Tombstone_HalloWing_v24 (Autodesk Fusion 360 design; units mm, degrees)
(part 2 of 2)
sketch "Sketch16" plane through (0, 0, 0) normal (1, 0, 0) x axis (0, 1, 0)
  curve K1 (-0.5, 161.7636) -> (4.5, 161.7636)
  line L1 (10, 161.7636) -> (4.5, 161.7636)
  line L2 (10, 180) -> (10, 161.7636)
  line L3 (-6, 180) -> (10, 180)
  line L4 (-6, 161.7636) -> (-6, 180)
  line L5 (-0.5, 161.7636) -> (-6, 161.7636)
  curve K2 (2, 168) -> (2, 177)
  curve K3 (7.5, 172.5) -> (-3.5, 172.5)
  line L6 (-2, 164.9114) -> (-2, 169.4114)
  line L7 (0.394, 166.2936) -> (-2, 164.9114)
  line L8 (2, 164) -> (0.394, 166.2936)
  curve K4 (-0.5, 171) -> (-0.5, 175)
  curve K5 (1.25, 173) -> (-2.25, 173)
  line L9 (2, 177) -> (2, 180)
  line L10 (3.4434, 169) -> (0.5566, 169)
  line L11 (2, 171.5) -> (3.4434, 169)
  line L12 (0.5566, 169) -> (2, 171.5)
  line L13 (2, 169) -> (2, 171.5)
  line L14 (2, 168) -> (2, 164)
  line L15 (2, 164) -> (3.606, 166.2936)
  line L16 (3.606, 166.2936) -> (6, 164.9114)
  line L17 (6, 164.9114) -> (6, 169.4114)
  closed curve K6 centre (2, 172.5)
  closed curve K7 centre (-0.5, 173)
  closed curve K8 centre (4.5, 173)
  point P9 (2, 177)
  point P10 (2, 168)
  point P11 (-3.5, 172.5)
  point P12 (7.5, 172.5)
  point P13 (-2, 169.4114)
  point P18 (-0.5, 175)
  point P19 (-0.5, 171)
  point P20 (-2.25, 173)
  point P21 (1.25, 173)
  point P22 (2, 180)
  point P28 (2, 169)
  point P32 (6, 169.4114)
  point P14 (-2, 164.9114)
  point P31 (6, 164.9114)
  point P15 (0.394, 166.2936)
  point P29 (3.606, 166.2936)
  point P16 (2, 164)
  point P30 (2, 164)
  point P23 (2, 177)
  point P27 (2, 171.5)
  point P8 (2, 172.5)
  vertical K2
  coincident K6 P9
  coincident K6 P10
  coincident K6 P11
  coincident K6 P12
  coincident K6 P13
  vertical L6
  coincident K7 P18
  coincident K7 P19
  coincident K7 P20
  coincident K7 P21
  midpoint L3 P22
  perpendicular L3 L9
  symmetric K7 L9 K8
  perpendicular K2 L10
  midpoint L10 P28
  vertical L13
  collinear K2 L13
  vertical L14
  symmetric P13 L14 P32
  symmetric P14 L14 P31
  symmetric P15 L14 P29
  symmetric P16 L14 P30
  coincident P9 P23
  dimension "d450" distance K6 = 9
  dimension "d451" = 11
  dimension "d452" = 3.5
  dimension "d453" distance K7 = 4
  dimension "d454" angle L11 L12 = 60
  dimension "d455" distance P27 P28 = 2.5
  dimension "d456" angle L8 L14 = 35
  dimension "d457" distance P10 P16 = 4
  dimension "d458" distance P13 P14 = 4.5
  dimension "d459" distance L6 L14 = 4
  dimension "d464" distance P22 P23 = 3
  dimension "d465" distance K3 K5 = 0.5
  dimension "d466" distance K2 K4 = 2.5
  dimension "d467" distance P8 P27 = 1
  dimension "d468" angle L6 L7 = 60
extrude "Extrude22" sketch "Sketch16" profile of K6 L6 L7 L8 K7 K8 L10 L11 L12 L15 L16 L17 blind 2
chamfer "Chamfer19" distance 1
extrude "Extrude23" cut of existing geometry blind -1
extrude "Extrude24" sketch "Sketch16" profile of K7 K8 L10 L11 L12 blind -0.5
chamfer "Chamfer20" distance 0.5
mirror "Mirror12" mirrorStitchTolerance 0.1
sketch "project face plate" plane through (0, -2, 0) normal (0, -1, 0) x axis (1, 0, 0)
  line L1 (52.2, 42) -> (52.2, 24)
  line L2 (54, 43) -> (53.2, 43)
  line L3 (53.2, 50) -> (54, 50)
  line L4 (52.2, 142) -> (52.2, 51)
  line L5 (54, 143) -> (53.2, 143)
  line L6 (53.2, 150) -> (54, 150)
  line L7 (52.2, 168.2) -> (52.2, 151)
  line L8 (37.9684, 170.2) -> (50.2, 170.2)
  line L9 (-50.2, 170.2) -> (-37.9684, 170.2)
  line L10 (-52.2, 151) -> (-52.2, 168.2)
  line L11 (-54, 150) -> (-53.2, 150)
  line L12 (-53.2, 143) -> (-54, 143)
  line L13 (-52.2, 51) -> (-52.2, 142)
  line L14 (-54, 50) -> (-53.2, 50)
  line L15 (-53.2, 43) -> (-54, 43)
  line L16 (-52.2, 24) -> (-52.2, 42)
  line L17 (50.2, 22) -> (-50.2, 22)
  line L18 (36, 37.2952) -> (36, 136.7048)
  line L19 (-36, 136.7048) -> (-36, 37.2952)
  line L20 (50.2, 168.2) -> (-50.2, 168.2)
  line L21 (50.2, 24) -> (50.2, 168.2)
  line L22 (-50.2, 24) -> (50.2, 24)
  line L23 (-50.2, 168.2) -> (-50.2, 24)
  circle C1 centre (13.8, 192.063) radius 2.5
  arc A1 centre (50.2, 24) radius 2 clockwise from (52.2, 24) to (50.2, 22)
  arc A2 centre (53.2, 42) radius 1 clockwise from (52.2, 42) to (53.2, 43)
  arc A3 centre (54, 46.5) radius 3.5 clockwise from (54, 50) to (54, 43)
  arc A4 centre (53.2, 51) radius 1 clockwise from (53.2, 50) to (52.2, 51)
  arc A5 centre (53.2, 142) radius 1 clockwise from (52.2, 142) to (53.2, 143)
  arc A6 centre (54, 146.5) radius 3.5 clockwise from (54, 150) to (54, 143)
  arc A7 centre (53.2, 151) radius 1 clockwise from (53.2, 150) to (52.2, 151)
  arc A8 centre (50.2, 168.2) radius 2 clockwise from (50.2, 170.2) to (52.2, 168.2)
  arc A9 centre (37.9684, 172.2) radius 2 clockwise from (37.9684, 170.2) to (35.9805, 171.9801)
  arc A10 centre (0, 168) radius 36.2 clockwise from (-35.9805, 171.9801) to (35.9805, 171.9801)
  arc A11 centre (-37.9684, 172.2) radius 2 clockwise from (-35.9805, 171.9801) to (-37.9684, 170.2)
  arc A12 centre (-50.2, 168.2) radius 2 clockwise from (-52.2, 168.2) to (-50.2, 170.2)
  arc A13 centre (-53.2, 151) radius 1 clockwise from (-52.2, 151) to (-53.2, 150)
  arc A14 centre (-54, 146.5) radius 3.5 clockwise from (-54, 143) to (-54, 150)
  arc A15 centre (-53.2, 142) radius 1 clockwise from (-53.2, 143) to (-52.2, 142)
  arc A16 centre (-53.2, 51) radius 1 clockwise from (-52.2, 51) to (-53.2, 50)
  arc A17 centre (-54, 46.5) radius 3.5 clockwise from (-54, 43) to (-54, 50)
  arc A18 centre (-53.2, 42) radius 1 clockwise from (-53.2, 43) to (-52.2, 42)
  arc A19 centre (-50.2, 24) radius 2 clockwise from (-50.2, 22) to (-52.2, 24)
  circle C2 centre (-54, 46.5) radius 1.75
  circle C3 centre (-54, 146.5) radius 1.75
  circle C4 centre (54, 46.5) radius 1.75
  circle C5 centre (54, 146.5) radius 1.75
  arc A20 centre (0, -56) radius 100 clockwise from (-36, 37.2952) to (36, 37.2952)
  arc A21 centre (0, 230) radius 100 clockwise from (36, 136.7048) to (-36, 136.7048)
  circle C6 centre (0, 168) radius 34.2
  point P36 (-50.2, 168.2)
  point P64 (-50.2, 168.2)
  point P26 (50.2, 168.2)
  point P65 (50.2, 168.2)
  point P5 (50.2, 24)
  point P66 (50.2, 24)
  point P57 (-50.2, 24)
  point P67 (-50.2, 24)
  coincident P36 P64
  coincident P26 P65
  coincident P5 P66
  coincident P57 P67
  concentric A10 C6
  dimension "d478" distance A10 C6 = 2
extrude "Extrude14" new body sketch "project face plate" profile of C1 L18 A20 L19 A21 L20 L21 L22 L23 C6 along normal blind 1 bodies "plate vinyl"
sketch "face plate vinyl" plane through (0, -3, 0) normal (0, -1, 0) x axis (1, 0, 0)
  curve K1 (0, 184.5) -> (-15.4989, 168.2)
  curve K2 (15.4989, 168.2) -> (0, 184.5)
  curve K3 (-15.4989, 168.2) -> (15.4989, 168.2)
  line L1 (-36, 136.7048) -> (-36, 37.2952)
  line L2 (36, 37.2952) -> (36, 136.7048)
  line L3 (-50.2, 168.2) -> (-34.1994, 168.2)
  line L4 (-50.2, 24) -> (-50.2, 168.2)
  line L5 (50.2, 24) -> (-50.2, 24)
  line L6 (50.2, 168.2) -> (50.2, 24)
  line L7 (34.1994, 168.2) -> (50.2, 168.2)
  circle C1 centre (13.8, 192.063) radius 2.5
  arc A1 centre (0, 230) radius 100 clockwise from (36, 136.7048) to (-36, 136.7048)
  arc A2 centre (0, -56) radius 100 clockwise from (-36, 37.2952) to (36, 37.2952)
  arc A3 centre (0, 168) radius 34.2 clockwise from (-34.1994, 168.2) to (34.1994, 168.2)
sketch "bottom lip" plane through (0, 28, 0) normal (0, -1, 0) x axis (1, 0, 0)
  line L1 (-55, 22) -> (55, 22)
  line L2 (45, 23.5) -> (-45, 23.5)
  line L3 (45, 22) -> (45, 23.5)
  line L4 (-45, 22) -> (45, 22)
  line L5 (-45, 23.5) -> (-45, 22)
  line L6 (36.8782, 171) -> (53, 171)
  line L7 (52.8, 170.8) -> (37.0782, 170.8)
  line L8 (52.8, 169.3) -> (52.8, 170.8)
  line L9 (37.0782, 169.3) -> (52.8, 169.3)
  line L10 (37.0782, 170.8) -> (37.0782, 169.3)
  line L11 (44.9391, 171) -> (44.9391, 170.8)
  line L12 (52.8, 169.3) -> (51.3, 169.3)
  line L13 (52.8, 155.3) -> (52.8, 169.3)
  line L14 (51.3, 155.3) -> (52.8, 155.3)
  line L15 (51.3, 169.3) -> (51.3, 155.3)
  point P14 (44.9391, 170.8)
  point P15 (44.9391, 171)
  point P12 (52.8, 169.3)
  point P17 (52.8, 169.3)
  point P4 (-45, 23.5)
  point P5 (45, 23.5)
  point P7 (-45, 22)
  point P10 (37.0782, 170.8)
  point P13 (37.0782, 169.3)
  point P9 (36.8782, 171)
  point P16 (51.3, 169.3)
  point P19 (51.3, 155.3)
  point P18 (52.8, 155.3)
  horizontal L2
  vertical L3
  horizontal L4
  vertical L5
  midpoint L1 L4
  horizontal L7
  vertical L8
  horizontal L9
  vertical L10
  midpoint L7 P14
  midpoint L6 P15
  vertical L11
  horizontal L12
  vertical L13
  horizontal L14
  vertical L15
  coincident P12 P17
  dimension "d483" distance P4 P5 = 90
  dimension "d484" distance P4 P7 = 1.5 (= "wallThickness")
  dimension "d497" distance P14 P15 = 0.2 (= "gap")
  dimension "d498" distance P10 P13 = 1.5 (= "wallThickness")
  dimension "d499" distance P9 L10 = 0.2 (= "gap")
  dimension "d502" distance P16 P19 = 14
  dimension "d503" distance P18 P19 = 1.5 (= "wallThickness")
extrude "Extrude7" add sketch "bottom lip" profile of L7 L8 L9 L10 L12 L13 L14 L15 along normal blind 3
draft "Draft3" Angle1 45 Angle2 0
mirror "Mirror3" mirrorStitchTolerance 0.1
extrude "Extrude4" add sketch "bottom lip" profile of L1 L2 L3 L4 L5 along normal blind 4
draft "Draft2" Angle1 45 Angle2 0
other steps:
extrude "Extrude1" new body sketch "Sketch1" along normal blind 0.1 named "d6_1" bodies "FIDUCIAL_1MM"
extrude "Extrude1" new body sketch "Sketch1" along normal blind 0.1 named "d8_1" bodies "MOUNTINGHOLE_2.5_PLATED"
extrude "Extrude1" new body sketch "Sketch1" along normal blind 0.1 named "d10_1" bodies "PCB_ALLI_LONG"
extrude "Extrude1" new body sketch "Sketch1" along normal blind 0.1 bodies "PCB_ALLI"
extrude "Extrude1" new body sketch "Sketch1" along normal blind 0.1 named "d32_1" bodies "FEATHERWING_SMT_NOHOLES"
extrude "Extrude1" new body sketch "Sketch1" along normal blind 0.1 named "d46_1" bodies "SOLDERJUMPER_2WAY_OPEN_NOPASTE"
extrude "Extrude1" new body sketch "Sketch1" along normal blind 0.1 named "d52_1" bodies "TESTPOINT_ROUND_1.5MM"
extrude "Extrude1" new body sketch "Sketch1" along normal blind 0.1 named "d62_1" bodies "PCBFEAT-REV-040"
extrude "Extrude1" new body sketch "Sketch1" along normal blind 0.1 named "d70_1" bodies "HALLOWINGM4_FRONT"
extrude "Extrude1" new body sketch "Sketch1" along normal blind 0.1 named "d72_1" bodies "HALLOWINGM4_BACK"
extrude "Extrude1" new body sketch "Sketch1" along normal blind 0.1 bodies "ALS-PT26-21C"
extrude "Extrude1" new body sketch "Sketch1" along normal blind 0.1 bodies "0603-NO"
extrude "Extrude1" new body sketch "Sketch1" along normal blind 0.1 named "d18_1" bodies "0805-NO"
extrude "Extrude1" new body sketch "Sketch1" along normal blind 0.1 named "d20_1" bodies "CHIPLED_0805_NOOUTLINE"
extrude "Extrude1" new body sketch "Sketch1" along normal blind 0.1 named "d22_1" bodies "BTN_KMR2_4.6X2.8"
extrude "Extrude1" new body sketch "Sketch1" along normal blind 0.1 named "d24_1" bodies "4UCONN_20329_V2"
extrude "Extrude1" new body sketch "Sketch1" along normal blind 0.1 named "d26_1" bodies "SOT23-5"
extrude "Extrude1" new body sketch "Sketch1" along normal blind 0.1 named "d28_1" bodies "JSTPH2"
extrude "Extrude1" new body sketch "Sketch1" along normal blind 0.1 named "d30_1" bodies "WS2812B_4020"
extrude "Extrude1" new body sketch "Sketch1" along normal blind 0.1 named "d34_1" bodies "SOT23-WIDE"
extrude "Extrude1" new body sketch "Sketch1" along normal blind 0.1 named "d36_1" bodies "JSTPH3"
extrude "Extrude1" new body sketch "Sketch1" along normal blind 0.1 named "d38_1" bodies "SOD-123"
extrude "Extrude1" new body sketch "Sketch1" along normal blind 0.1 named "d40_1" bodies "SOT23-R"
extrude "Extrude1" new body sketch "Sketch1" along normal blind 0.1 named "d42_1" bodies "RESPACK_4X0603"
extrude "Extrude1" new body sketch "Sketch1" along normal blind 0.1 named "d44_1" bodies "JSTPH4"
extrude "Extrude1" new body sketch "Sketch1" along normal blind 0.1 named "d48_1" bodies "SOD-323"
extrude "Extrude1" new body sketch "Sketch1" along normal blind 0.1 named "d50_1" bodies "53398-0271"
extrude "Extrude1" new body sketch "Sketch1" along normal blind 0.1 named "d54_1" bodies "SOIC8_208MIL"
extrude "Extrude1" new body sketch "Sketch1" along normal blind 0.1 bodies "PQFN64-1"
extrude "Extrude1" new body sketch "Sketch1" along normal blind 0.1 bodies "SOT23-6"
extrude "Extrude1" new body sketch "Sketch1" along normal blind 0.1 named "d60_1" bodies "SOT363"
extrude "Extrude1" new body sketch "Sketch1" along normal blind 0.1 named "d64_1" bodies "EG1390"
extrude "Extrude1" new body sketch "Sketch1" along normal blind 0.1 named "d66_1" bodies "LGA12_2X2MM"
extrude "Extrude1" new body sketch "Sketch1" along normal blind 0.1 named "d68_1" bodies "TFT_1.54IN_240X240_HANDSOLDER"
base_feature "Base Feature1" sketch "Sketch1"
base_feature "Base Feature1" sketch "Sketch1"
base_feature "Base Feature1" sketch "Sketch1"
base_feature "Base Feature1" sketch "Sketch1"
base_feature "Base Feature1" sketch "Sketch1"
base_feature "Base Feature1" sketch "Sketch1"
base_feature "Base Feature1" sketch "Sketch1"
base_feature "Base Feature1" sketch "Sketch1"
base_feature "Base Feature1" sketch "Sketch1"
base_feature "Base Feature1" sketch "Sketch1"
base_feature "Base Feature1" sketch "Sketch1"
base_feature "Base Feature1" sketch "Sketch1"
base_feature "Base Feature1" sketch "Sketch1"
base_feature "Base Feature1" sketch "Sketch1"
base_feature "Base Feature1" sketch "Sketch1"
base_feature "Base Feature1" sketch "Sketch1"
base_feature "Base Feature1" sketch "Sketch1"
base_feature "Base Feature1" sketch "Sketch1"
base_feature "Base Feature1" sketch "Sketch1"
base_feature "Base Feature1" sketch "Sketch1"
base_feature "Base Feature1" sketch "Sketch1"
base_feature "Base Feature1" sketch "Sketch1"
base_feature "Base Feature1" sketch "Sketch1"
base_feature "Base Feature1" sketch "Sketch1"
extrude "Extrude1" new body sketch "Sketch1" along normal blind 1.57 named "d2_1" bodies "Board"
extrude "Extrude2" sketch "Sketch2" blind 1.57 named "d4_1"
create_component "CreateComponent1"
create_component "CreateComponent2"
create_component "CreateComponent1"
create_component "CreateComponent2"
create_component "CreateComponent3"
create_component "CreateComponent4"
create_component "CreateComponent5"
joint_origin "JointOrigin6"
create_component "CreateComponent3"
create_component "CreateComponent6"
create_component "CreateComponent1" OffsetX 0 named "d78_1" OffsetY 0 named "d79_1" OffsetZ 0 named "d80_1" AngleZ 0 named "d81_1"
create_component "CreateComponent1"
sketch "Sketch1" plane through (0, 0, 0) normal (0, 0, 1) x axis (1, 0, 0)
  line L1 (-7.62, -30.226) -> (7.62, -30.226)
  line L2 (-12.751, -20.477) -> (-12.751, -25.222)
  line L3 (-23.789, -15.158) -> (-15.819, -16.739)
  line L4 (-25.4, 16.814) -> (-25.4, -13.165)
  line L5 (-16.203, 27.633) -> (-24.312, 19.505)
  line L6 (-2.54, 29.87) -> (-10.809, 29.87)
  line L7 (-2.032, 29.362) -> (-2.54, 29.87)
  line L8 (2.032, 29.362) -> (-2.032, 29.362)
  line L9 (2.54, 29.87) -> (2.032, 29.362)
  line L10 (10.717, 29.87) -> (2.54, 29.87)
  line L11 (24.23, 19.531) -> (16.099, 27.645)
  line L12 (25.4, -13.168) -> (25.4, 16.834)
  line L13 (15.815, -16.737) -> (23.716, -15.161)
  line L14 (12.751, -25.222) -> (12.751, -20.473)
  arc A1 centre (-7.6835, -25.1585) radius 5.0679 clockwise from (-7.62, -30.226) to (-12.751, -25.222)
  arc A2 centre (-16.5612, -20.4763) radius 3.8102 clockwise from (-15.819, -16.739) to (-12.751, -20.477)
  arc A3 centre (-23.3809, -13.1805) radius 2.0192 clockwise from (-23.789, -15.158) to (-25.4, -13.165)
  arc A4 centre (-21.6026, 16.8441) radius 3.7975 clockwise from (-25.4, 16.814) to (-24.312, 19.505)
  arc A5 centre (-10.8099, 22.2505) radius 7.6195 clockwise from (-16.203, 27.633) to (-10.809, 29.87)
  arc A6 centre (10.718, 22.2507) radius 7.6193 clockwise from (10.7151, 29.87) to (16.099, 27.645)
  arc A7 centre (21.5645, 16.7724) radius 3.836 clockwise from (24.23, 19.531) to (25.4, 16.834)
  arc A8 centre (23.342, -13.137) radius 2.0582 clockwise from (25.4, -13.168) to (23.716, -15.161)
  arc A9 centre (16.5604, -20.4728) radius 3.8094 clockwise from (12.751, -20.473) to (15.815, -16.737)
  arc A10 centre (7.6835, -25.1585) radius 5.0679 clockwise from (12.751, -25.222) to (7.62, -30.226)
  circle C1 centre (8.89, -18.161) radius 1.27
  circle C2 centre (-8.89, -18.161) radius 1.27
  circle C3 centre (-17.082, 22.606) radius 1.5875
  circle C4 centre (17.208, 22.606) radius 1.5875
  dimension "d74_1" OffsetX = 0
  dimension "d75_1" OffsetY = 0
  dimension "d76_1" OffsetZ = 0
  dimension "d77_1" AngleZ = 0
canvas "Canvas1"
canvas "Canvas2"
sketch "Sketch2" plane through (0, 0, 0) normal (0, 0, 1) x axis (1, 0, 0)
  line L1 (3.5, 26.65) -> (3.7, 26.65)
  line L2 (3.15, 27.55) -> (3.15, 27)
  line L3 (3.7, 27.95) -> (3.5, 27.95)
  line L4 (4.05, 27) -> (4.05, 27.55)
  line L5 (-4.05, 27.6) -> (-4.05, 27)
  line L6 (-3.15, 27) -> (-3.15, 27.6)
  circle C1 centre (-6.414, 18.288) radius 0.25
  circle C2 centre (-11.43, 14.16) radius 0.25
  circle C3 centre (-1.27, 15.748) radius 0.25
  circle C4 centre (4.191, 15.558) radius 0.25
  circle C5 centre (-3.302, 4.191) radius 0.25
  circle C6 centre (0.254, -0.889) radius 0.25
  circle C7 centre (4.699, 11.684) radius 0.25
  circle C8 centre (10.541, 18.732) radius 0.25
  circle C9 centre (-11.494, 22.06) radius 0.25
  circle C10 centre (9.716, 22.542) radius 0.25
  circle C11 centre (14.097, 27.305) radius 0.25
  circle C12 centre (-0.064, -13.716) radius 0.25
  circle C13 centre (2.984, -19.05) radius 0.25
  circle C14 centre (-22.225, -8.636) radius 0.25
  circle C15 centre (-17.526, -4.953) radius 0.25
  circle C16 centre (-18.161, -11.557) radius 0.25
  circle C17 centre (-3.556, 18.86) radius 0.25
  circle C18 centre (8.065, 16.066) radius 0.25
  circle C19 centre (17.59, 17.59) radius 0.25
  circle C20 centre (16.256, 16.574) radius 0.25
  circle C21 centre (16.51, 14.478) radius 0.25
  circle C22 centre (-5.715, 0.698) radius 0.25
  circle C23 centre (0, 4.191) radius 0.25
  circle C24 centre (-6.922, 13.018) radius 0.25
  circle C25 centre (16.828, -2.35) radius 0.25
  circle C26 centre (18.352, 0.444) radius 0.25
  circle C27 centre (19.812, 22.162) radius 0.25
  circle C28 centre (14.034, 21.082) radius 0.25
  circle C29 centre (21.844, -4.064) radius 0.25
  circle C30 centre (23.686, -14.288) radius 0.25
  circle C31 centre (11.24, -11.303) radius 0.25
  circle C32 centre (11.366, -8.509) radius 0.25
  circle C33 centre (6.286, -11.557) radius 0.25
  circle C34 centre (-4.128, -12.192) radius 0.25
  circle C35 centre (-20.066, 14.922) radius 0.25
  circle C36 centre (-23.622, 7.302) radius 0.25
  circle C37 centre (-21.336, 10.35) radius 0.25
  circle C38 centre (-24.638, 13.906) radius 0.25
  circle C39 centre (-22.352, 19.622) radius 0.25
  circle C40 centre (-5.27, -16.764) radius 0.25
  circle C41 centre (-16.764, 4.382) radius 0.25
  circle C42 centre (-20.193, 6.032) radius 0.25
  circle C43 centre (-24.638, 9.716) radius 0.25
  circle C44 centre (-22.733, -0.318) radius 0.25
  circle C45 centre (-2.921, 17.145) radius 0.25
  circle C46 centre (22.416, 7.556) radius 0.25
  circle C47 centre (22.416, 12.636) radius 0.25
  circle C48 centre (11.366, -3.429) radius 0.25
  circle C49 centre (11.366, 1.651) radius 0.25
  circle C50 centre (11.366, -5.969) radius 0.25
  circle C51 centre (1.524, 0.254) radius 0.25
  circle C52 centre (6.414, -13.335) radius 0.25
  circle C53 centre (4.935, 6.922) radius 0.25
  circle C54 centre (-11.43, -4.699) radius 0.25
  circle C55 centre (4.488, 5.822) radius 0.25
  circle C56 centre (-11.43, -6.858) radius 0.25
  circle C57 centre (6.125, 2.225) radius 0.25
  circle C58 centre (-11.43, -2.667) radius 0.25
  circle C59 centre (-11.443, 0.318) radius 0.25
  circle C60 centre (-11.43, -16.129) radius 0.25
  circle C61 centre (-11.43, 2.921) radius 0.25
  circle C62 centre (-11.43, 1.651) radius 0.25
  circle C63 centre (-11.43, 5.524) radius 0.25
  circle C64 centre (-15.938, -1.651) radius 0.25
  circle C65 centre (-11.494, -0.889) radius 0.25
  circle C66 centre (-16.256, -0.254) radius 0.25
  circle C67 centre (-1.651, -8.192) radius 0.25
  circle C68 centre (6.032, -4.926) radius 0.25
  circle C69 centre (-3.175, 15.494) radius 0.25
  circle C70 centre (0.025, 8.226) radius 0.25
  circle C71 centre (5.842, 6.223) radius 0.25
  circle C72 centre (3.556, 13.716) radius 0.25
  circle C73 centre (21.971, 17.716) radius 0.25
  circle C74 centre (-5.778, 15.304) radius 0.25
  circle C75 centre (4.254, -13.97) radius 0.25
  circle C76 centre (-5.767, -3.366) radius 0.25
  circle C77 centre (3.706, -10.164) radius 0.25
  circle C78 centre (7.112, 22.352) radius 0.25
  circle C79 centre (7.302, 9.271) radius 0.25
  circle C80 centre (4, 19.368) radius 0.25
  circle C81 centre (-11.43, 13.051) radius 0.25
  circle C82 centre (-16.51, 13.783) radius 0.25
  circle C83 centre (4.191, -19.029) radius 0.25
  circle C84 centre (21.209, -9.97) radius 0.25
  circle C85 centre (5.605, -14.986) radius 0.25
  circle C86 centre (21.272, -8.001) radius 0.25
  circle C87 centre (-11.43, -10.986) radius 0.25
  circle C88 centre (1.558, -7.365) radius 0.25
  circle C89 centre (-11.366, -8.636) radius 0.25
  circle C90 centre (1.083, -6.011) radius 0.25
  circle C91 centre (-0.133, 21.336) radius 0.25
  circle C92 centre (6.964, 6.199) radius 0.25
  circle C93 centre (1.054, 20.993) radius 0.25
  circle C94 centre (6.858, 4.89) radius 0.25
  circle C95 centre (1.697, 7.856) radius 0.25
  circle C96 centre (-11.43, 23.241) radius 0.25
  circle C97 centre (13.398, 25.527) radius 0.25
  circle C98 centre (11.303, 25.844) radius 0.25
  circle C99 centre (2.629, 6.54) radius 0.25
  circle C100 centre (6.837, 11.112) radius 0.25
  circle C101 centre (-4.445, 22.098) radius 0.25
  circle C102 centre (2.011, 19.488) radius 0.25
  circle C103 centre (14.922, 15.684) radius 0.25
  circle C104 centre (21.59, 19.346) radius 0.25
  circle C105 centre (21.942, 1.891) radius 0.25
  circle C106 centre (-21.003, -14.322) radius 0.25
  circle C107 centre (-23.241, 14.732) radius 0.25
  circle C108 centre (20.32, -12.645) radius 0.25
  circle C109 centre (-24.236, -0.41) radius 0.25
  circle C110 centre (20.51, 20.51) radius 0.25
  circle C111 centre (-2.54, -18.86) radius 0.25
  circle C112 centre (4.695, -5.524) radius 0.25
  circle C113 centre (-1.633, -12.936) radius 0.25
  circle C114 centre (-2.274, 6.344) radius 0.197
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create_component "CreateComponent2" sketch "Sketch1"
sketch "Sketch1" plane through (0, 0, 0) normal (0, 0, 1) x axis (1, 0, 0)
  line L1 (0.75, -0.75) -> (-0.75, -0.75)
  line L2 (0.75, 0.75) -> (0.75, -0.75)
  line L3 (-0.75, 0.75) -> (0.75, 0.75)
  line L4 (-0.75, -0.75) -> (-0.75, 0.75)
create_component "CreateComponent3" sketch "Sketch1"
sketch "Sketch1" plane through (0, 0, 0) normal (0, 0, 1) x axis (1, 0, 0)
  line L1 (2, -2) -> (-2, -2)
  line L2 (2, 2) -> (2, -2)
  line L3 (-2, 2) -> (2, 2)
  line L4 (-2, -2) -> (-2, 2)
create_component "CreateComponent4" sketch "Sketch1"
sketch "Sketch1" plane through (0, 0, 0) normal (0, 0, 1) x axis (1, 0, 0)
  line L1 (2.54, -1.651) -> (-2.54, -1.651)
  line L2 (2.54, 6.769) -> (2.54, -1.651)
  line L3 (-2.54, 6.769) -> (2.54, 6.769)
  line L4 (-2.54, -1.651) -> (-2.54, 6.769)
create_component "CreateComponent5" sketch "Sketch1"
sketch "Sketch1" plane through (0, 0, 0) normal (0, 0, 1) x axis (1, 0, 0)
  line L1 (2.54, -1.651) -> (-2.54, -1.651)
  line L2 (2.54, 2.959) -> (2.54, -1.651)
  line L3 (-2.54, 2.959) -> (2.54, 2.959)
  line L4 (-2.54, -1.651) -> (-2.54, 2.959)
create_component "CreateComponent6" sketch "Sketch1"
sketch "Sketch1" plane through (0, 0, 0) normal (0, 0, 1) x axis (1, 0, 0)
  line L1 (1.2, -1.2) -> (-1.2, -1.2)
  line L2 (1.2, 1.2) -> (1.2, -1.2)
  line L3 (-1.2, 1.2) -> (1.2, 1.2)
  line L4 (-1.2, -1.2) -> (-1.2, 1.2)
create_component "CreateComponent7" sketch "Sketch1"
sketch "Sketch1" plane through (0, 0, 0) normal (0, 0, 1) x axis (1, 0, 0)
  line L1 (0.83, -0.47) -> (-0.838, -0.47)
  line L2 (0.83, 0.48) -> (0.83, -0.47)
  line L3 (-0.838, 0.48) -> (0.83, 0.48)
  line L4 (-0.838, -0.47) -> (-0.838, 0.48)
create_component "CreateComponent8" sketch "Sketch1"
sketch "Sketch1" plane through (0, 0, 0) normal (0, 0, 1) x axis (1, 0, 0)
  line L1 (1.106, -0.724) -> (-1.092, -0.724)
  line L2 (1.106, 0.726) -> (1.106, -0.724)
  line L3 (-1.092, 0.726) -> (1.106, 0.726)
  line L4 (-1.092, -0.724) -> (-1.092, 0.726)
create_component "CreateComponent9" sketch "Sketch1"
sketch "Sketch1" plane through (0, 0, 0) normal (0, 0, 1) x axis (1, 0, 0)
  line L1 (0.625, -1.3334) -> (-0.625, -1.3334)
  line L2 (0.625, 1.3334) -> (0.625, -1.3334)
  line L3 (-0.625, 1.3334) -> (0.625, 1.3334)
  line L4 (-0.625, -1.3334) -> (-0.625, 1.3334)
create_component "CreateComponent10" sketch "Sketch1"
sketch "Sketch1" plane through (0, 0, 0) normal (0, 0, 1) x axis (1, 0, 0)
  line L1 (2.1, -1.525) -> (-2.1, -1.525)
  line L2 (2.1, 1.525) -> (2.1, -1.525)
  line L3 (-2.1, 1.525) -> (2.1, 1.525)
  line L4 (-2.1, -1.525) -> (-2.1, 1.525)
create_component "CreateComponent11" sketch "Sketch1"
sketch "Sketch1" plane through (0, 0, 0) normal (0, 0, 1) x axis (1, 0, 0)
  line L1 (4.35, -4.9) -> (-4.05, -4.9)
  line L2 (4.35, 1.3) -> (4.35, -4.9)
  line L3 (-4.05, 1.3) -> (4.35, 1.3)
  line L4 (-4.05, -4.9) -> (-4.05, 1.3)
create_component "CreateComponent12" sketch "Sketch1"
sketch "Sketch1" plane through (0, 0, 0) normal (0, 0, 1) x axis (1, 0, 0)
  line L1 (1.65, -1.5) -> (-1.65, -1.5)
  line L2 (1.65, 1.5) -> (1.65, -1.5)
  line L3 (-1.65, 1.5) -> (1.65, 1.5)
  line L4 (-1.65, -1.5) -> (-1.65, 1.5)
create_component "CreateComponent13" sketch "Sketch1"
sketch "Sketch1" plane through (0, 0, 0) normal (0, 0, 1) x axis (1, 0, 0)
  line L1 (4, -4.5) -> (-4, -4.5)
  line L2 (4, 3) -> (4, -4.5)
  line L3 (-4, 3) -> (4, 3)
  line L4 (-4, -4.5) -> (-4, 3)
create_component "CreateComponent14" sketch "Sketch1"
sketch "Sketch1" plane through (0, 0, 0) normal (0, 0, 1) x axis (1, 0, 0)
  line L1 (2, -1) -> (-2, -1)
  line L2 (2, 1) -> (2, -1)
  line L3 (-2, 1) -> (2, 1)
  line L4 (-2, -1) -> (-2, 1)
create_component "CreateComponent15" sketch "Sketch1"
sketch "Sketch1" plane through (0, 0, 0) normal (0, 0, 1) x axis (1, 0, 0)
  line L1 (50.8, -4.064) -> (0, -4.064)
  line L2 (50.8, 26.924) -> (50.8, -4.064)
  line L3 (0, 26.924) -> (50.8, 26.924)
  line L4 (0, -4.064) -> (0, 26.924)
create_component "CreateComponent16" sketch "Sketch1"
sketch "Sketch1" plane through (0, 0, 0) normal (0, 0, 1) x axis (1, 0, 0)
  line L1 (1.672, -1.295) -> (-1.672, -1.295)
  line L2 (1.672, 1.295) -> (1.672, -1.295)
  line L3 (-1.672, 1.295) -> (1.672, 1.295)
  line L4 (-1.672, -1.295) -> (-1.672, 1.295)
create_component "CreateComponent17" sketch "Sketch1"
sketch "Sketch1" plane through (0, 0, 0) normal (0, 0, 1) x axis (1, 0, 0)
  line L1 (5, -3.5) -> (-5, -3.5)
  line L2 (5, 4) -> (5, -3.5)
  line L3 (-5, 4) -> (5, 4)
  line L4 (-5, -3.5) -> (-5, 4)
create_component "CreateComponent18" sketch "Sketch1"
sketch "Sketch1" plane through (0, 0, 0) normal (0, 0, 1) x axis (1, 0, 0)
  line L1 (1.723, -0.7) -> (-1.723, -0.7)
  line L2 (1.723, 0.7) -> (1.723, -0.7)
  line L3 (-1.723, 0.7) -> (1.723, 0.7)
  line L4 (-1.723, -0.7) -> (-1.723, 0.7)
create_component "CreateComponent19" sketch "Sketch1"
sketch "Sketch1" plane through (0, 0, 0) normal (0, 0, 1) x axis (1, 0, 0)
  line L1 (1.572, -1.295) -> (-1.572, -1.295)
  line L2 (1.572, 1.295) -> (1.572, -1.295)
  line L3 (-1.572, 1.295) -> (1.572, 1.295)
  line L4 (-1.572, -1.295) -> (-1.572, 1.295)
create_component "CreateComponent20" sketch "Sketch1"
sketch "Sketch1" plane through (0, 0, 0) normal (0, 0, 1) x axis (1, 0, 0)
  line L1 (1.9, -1.4) -> (-1.9, -1.4)
  line L2 (1.9, 1.4) -> (1.9, -1.4)
  line L3 (-1.9, 1.4) -> (1.9, 1.4)
  line L4 (-1.9, -1.4) -> (-1.9, 1.4)
create_component "CreateComponent21" sketch "Sketch1"
sketch "Sketch1" plane through (0, 0, 0) normal (0, 0, 1) x axis (1, 0, 0)
  line L1 (6, -4.5) -> (-6, -4.5)
  line L2 (6, 3) -> (6, -4.5)
  line L3 (-6, 3) -> (6, 3)
  line L4 (-6, -4.5) -> (-6, 3)
create_component "CreateComponent22" sketch "Sketch1"
sketch "Sketch1" plane through (0, 0, 0) normal (0, 0, 1) x axis (1, 0, 0)
  line L1 (2.286, -1.016) -> (-2.286, -1.016)
  line L2 (2.286, 1.016) -> (2.286, -1.016)
  line L3 (-2.286, 1.016) -> (2.286, 1.016)
  line L4 (-2.286, -1.016) -> (-2.286, 1.016)
create_component "CreateComponent23" sketch "Sketch1"
sketch "Sketch1" plane through (0, 0, 0) normal (0, 0, 1) x axis (1, 0, 0)
  line L1 (1, -0.7) -> (-1, -0.7)
  line L2 (1, 0.7) -> (1, -0.7)
  line L3 (-1, 0.7) -> (1, 0.7)
  line L4 (-1, -0.7) -> (-1, 0.7)
create_component "CreateComponent24" sketch "Sketch1"
sketch "Sketch1" plane through (0, 0, 0) normal (0, 0, 1) x axis (1, 0, 0)
  line L1 (3.75, -1.583) -> (-3.75, -1.583)
  line L2 (3.75, 2.792) -> (3.75, -1.583)
  line L3 (-3.75, 2.792) -> (3.75, 2.792)
  line L4 (-3.75, -1.583) -> (-3.75, 2.792)
create_component "CreateComponent25" sketch "Sketch1"
sketch "Sketch1" plane through (0, 0, 0) normal (0, 0, 1) x axis (1, 0, 0)
  line L1 (1, -1) -> (-1, -1)
  line L2 (1, 1) -> (1, -1)
  line L3 (-1, 1) -> (1, 1)
  line L4 (-1, -1) -> (-1, 1)
create_component "CreateComponent26" sketch "Sketch1"
sketch "Sketch1" plane through (0, 0, 0) normal (0, 0, 1) x axis (1, 0, 0)
  line L1 (2.4, -3.815) -> (-2.4, -3.815)
  line L2 (2.4, 3.815) -> (2.4, -3.815)
  line L3 (-2.4, 3.815) -> (2.4, 3.815)
  line L4 (-2.4, -3.815) -> (-2.4, 3.815)
create_component "CreateComponent27" sketch "Sketch1"
sketch "Sketch1" plane through (0, 0, 0) normal (0, 0, 1) x axis (1, 0, 0)
  line L1 (4.4, -4.4) -> (-5.216, -4.4)
  line L2 (4.4, 5.216) -> (4.4, -4.4)
  line L3 (-5.216, 5.216) -> (4.4, 5.216)
  line L4 (-5.216, -4.4) -> (-5.216, 5.216)
create_component "CreateComponent28" sketch "Sketch1"
sketch "Sketch1" plane through (0, 0, 0) normal (0, 0, 1) x axis (1, 0, 0)
  line L1 (1.45, -1.5) -> (-1.45, -1.5)
  line L2 (1.45, 1.5) -> (1.45, -1.5)
  line L3 (-1.45, 1.5) -> (1.45, 1.5)
  line L4 (-1.45, -1.5) -> (-1.45, 1.5)
create_component "CreateComponent29" sketch "Sketch1"
sketch "Sketch1" plane through (0, 0, 0) normal (0, 0, 1) x axis (1, 0, 0)
  line L1 (1.1, -1.05) -> (-1.6, -1.05)
  line L2 (1.1, 1.05) -> (1.1, -1.05)
  line L3 (-1.6, 1.05) -> (1.1, 1.05)
  line L4 (-1.6, -1.05) -> (-1.6, 1.05)
create_component "CreateComponent30" sketch "Sketch1"
sketch "Sketch1" plane through (0, 0, 0) normal (0, 0, 1) x axis (1, 0, 0)
  line L1 (0.898, -0.898) -> (-0.898, -0.898)
  line L2 (0.898, 0.898) -> (0.898, -0.898)
  line L3 (-0.898, 0.898) -> (0.898, 0.898)
  line L4 (-0.898, -0.898) -> (-0.898, 0.898)
create_component "CreateComponent31" sketch "Sketch1"
sketch "Sketch1" plane through (0, 0, 0) normal (0, 0, 1) x axis (1, 0, 0)
  line L1 (3.6, -1.75) -> (-3.6, -1.75)
  line L2 (3.6, 1.75) -> (3.6, -1.75)
  line L3 (-3.6, 1.75) -> (3.6, 1.75)
  line L4 (-3.6, -1.75) -> (-3.6, 1.75)
create_component "CreateComponent32" sketch "Sketch1"
sketch "Sketch1" plane through (0, 0, 0) normal (0, 0, 1) x axis (1, 0, 0)
  line L1 (1.1, -1.1) -> (-1.6, -1.1)
  line L2 (1.1, 1.1) -> (1.1, -1.1)
  line L3 (-1.6, 1.1) -> (1.1, 1.1)
  line L4 (-1.6, -1.1) -> (-1.6, 1.1)
create_component "CreateComponent33" sketch "Sketch1"
sketch "Sketch1" plane through (0, 0, 0) normal (0, 0, 1) x axis (1, 0, 0)
  line L1 (15.76, -17.1) -> (-15.76, -17.1)
  line L2 (15.76, 17.64) -> (15.76, -17.1)
  line L3 (-15.76, 17.64) -> (15.76, 17.64)
  line L4 (-15.76, -17.1) -> (-15.76, 17.64)
create_component "CreateComponent34" sketch "Sketch1"
sketch "Sketch1" plane through (0, 0, 0) normal (0, 0, 1) x axis (1, 0, 0)
  line L1 (49.837, 1.302) -> (0.922, 1.302)
  line L2 (49.837, 58.177) -> (49.837, 1.302)
  line L3 (0.922, 58.177) -> (49.837, 58.177)
  line L4 (0.922, 1.302) -> (0.922, 58.177)
create_component "CreateComponent35" sketch "Sketch1"
sketch "Sketch1" plane through (0, 0, 0) normal (0, 0, 1) x axis (1, 0, 0)
  line L1 (49.055, 3.842) -> (0.328, 3.842)
  line L2 (49.055, 56.78) -> (49.055, 3.842)
  line L3 (0.328, 56.78) -> (49.055, 56.78)
  line L4 (0.328, 3.842) -> (0.328, 56.78)
as_built_joint "As-built1"
create_component "CreateComponent36"
create_component "CreateComponent37"
joint_origin "JointOrigin2" OffsetX 0 named "d86_1" OffsetY 0 named "d87_1" OffsetZ 0 named "d88_1" AngleZ 0 named "d89_1"
joint_origin "JointOrigin2" OffsetX 0 named "d90_1" OffsetY 0 named "d91_1" OffsetZ 0 named "d92_1" AngleZ 0 named "d93_1"
create_component "CreateComponent1"
create_component "CreateComponent2"
named bodies: "plate", "frame", "back cover", "frame-face", "eye-ring", "plate vinyl", "Board", "FIDUCIAL_1MM", "MOUNTINGHOLE_2.5_PLATED", "PCB_ALLI_LONG", "PCB_ALLI", "ALS-PT26-21C", "0603-NO", "0805-NO", "CHIPLED_0805_NOOUTLINE", "BTN_KMR2_4.6X2.8", "4UCONN_20329_V2", "SOT23-5", "JSTPH2", "WS2812B_4020", "FEATHERWING_SMT_NOHOLES", "SOT23-WIDE", "JSTPH3", "SOD-123", "SOT23-R", "RESPACK_4X0603", "JSTPH4", "SOLDERJUMPER_2WAY_OPEN_NOPASTE", "SOD-323", "53398-0271", "TESTPOINT_ROUND_1.5MM", "SOIC8_208MIL", "PQFN64-1", "SOT23-6", "SOT363", "PCBFEAT-REV-040", "EG1390", "LGA12_2X2MM", "TFT_1.54IN_240X240_HANDSOLDER", "HALLOWINGM4_FRONT", "HALLOWINGM4_BACK"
